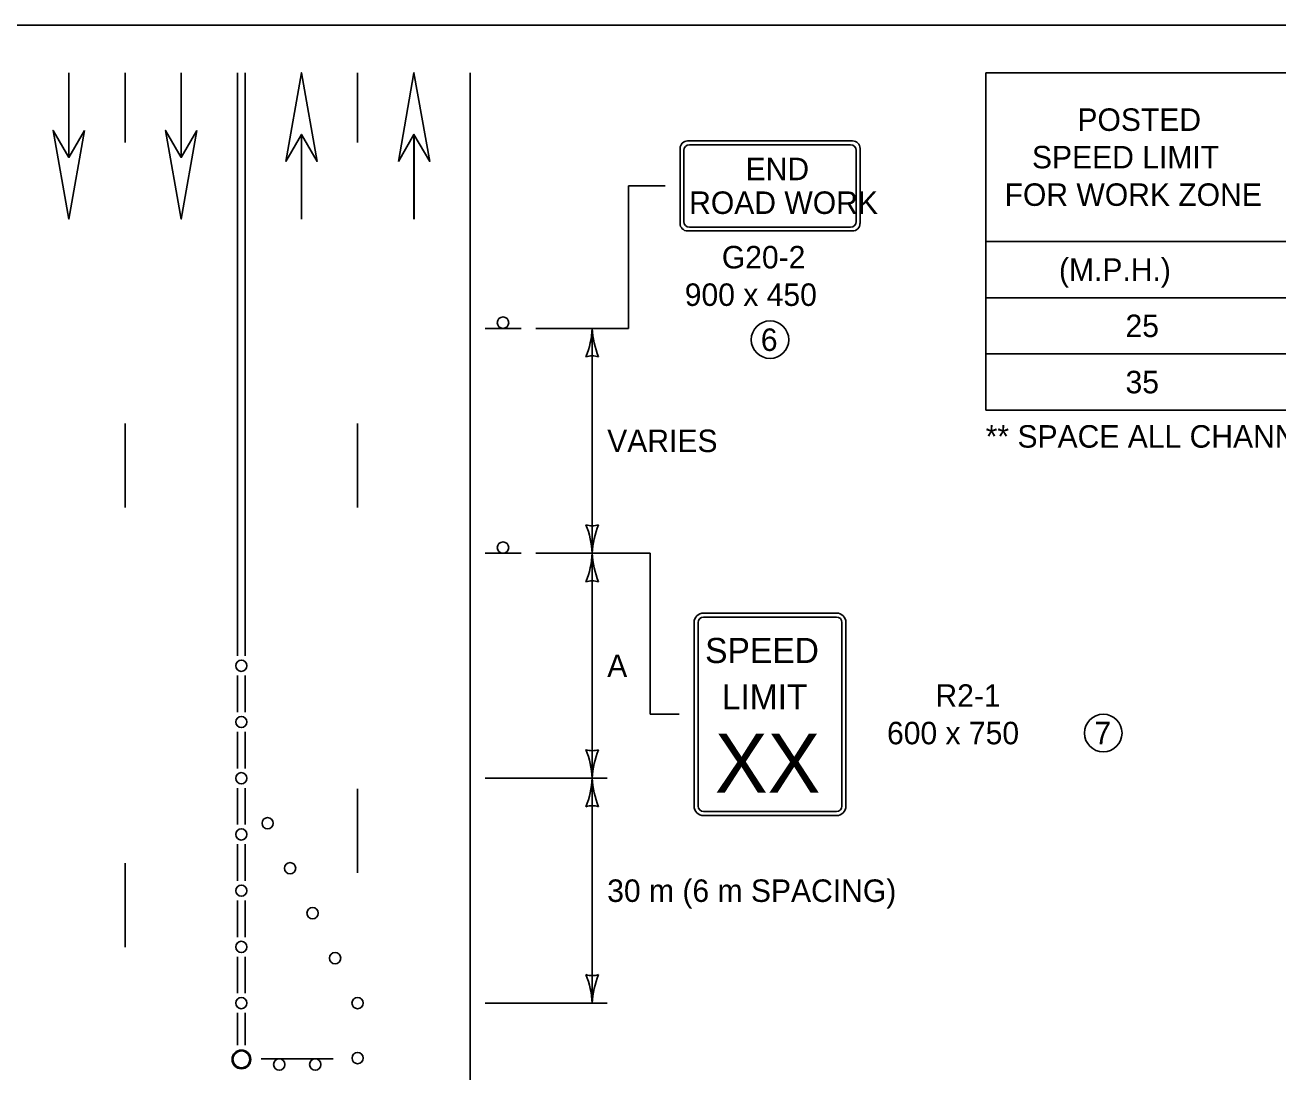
# Model space of a CAD drawing. Extents: x 49991.4 to 50021, y 49987.6 to 50011.4.
# Drawn here: x 50009.922 to 50013.265, y 49996.207 to 49998.999 of the extents above; entities that cross this region are included whole.
import ezdxf

# ---------------------------------------------------------------- set-up
doc = ezdxf.new("R2010")
doc.units = 0
for name, color, linetype in [('Level 1', 7, 'Continuous'), ('Level 2', 7, 'Continuous'), ('Level 3', 7, 'Continuous')]:
    doc.layers.add(name, color=color, linetype=linetype)

msp = doc.modelspace()

# ---------------------------------------------------------------- linework, layer by layer
at = {"layer": 'Level 1'}
for p, q in [((50010.0383, 49998.8719), (50010.0383, 49998.646)), ((50010.0387, 49998.8719), (50010.0387, 49998.646)), ((50010.1892, 49998.686), (50010.1892, 49998.8719)), ((50010.3383, 49998.8719), (50010.3383, 49998.646)), ((50010.3387, 49998.8719), (50010.3387, 49998.646)), ((50010.489, 49997.3163), (50010.489, 49998.8719)), ((50010.509, 49997.3163), (50010.509, 49998.8719)), ((50010.8092, 49998.686), (50010.8092, 49998.8719)), ((50011.109, 49995.0313), (50011.109, 49998.8719)), ((50010.6591, 49998.4818), (50010.6591, 49998.7077)), ((50010.6595, 49998.4818), (50010.6595, 49998.7077)), ((50010.9595, 49998.4818), (50010.9595, 49998.7077)), ((50010.9599, 49998.4818), (50010.9599, 49998.7077)), ((50011.6695, 49998.47), (50011.6695, 49998.67)), ((50011.6795, 49998.475), (50011.6795, 49998.665)), ((50012.1295, 49998.69), (50011.6895, 49998.69)), ((50012.1245, 49998.68), (50011.6945, 49998.68)), ((50012.1395, 49998.665), (50012.1395, 49998.475)), ((50012.1495, 49998.67), (50012.1495, 49998.47)), ((50012.1294, 49998.45), (50011.6894, 49998.45)), ((50012.1245, 49998.46), (50011.6945, 49998.46)), ((50011.245, 49998.1901), (50011.149, 49998.1901)), ((50010.1892, 49997.712), (50010.1892, 49997.936)), ((50010.8092, 49997.712), (50010.8092, 49997.936)), ((50011.245, 49997.5901), (50011.149, 49997.5901)), ((50011.7322, 49997.4307), (50012.0866, 49997.4307)), ((50011.9094, 49997.4307), (50011.9094, 49997.4307)), ((50011.7068, 49996.9158), (50011.7068, 49997.4053)), ((50011.7174, 49996.9158), (50011.7174, 49997.4053)), ((50011.7322, 49997.4201), (50012.0866, 49997.4201)), ((50012.1014, 49997.4053), (50012.1014, 49996.9158)), ((50012.1119, 49997.4053), (50012.1119, 49996.9158)), ((50010.4888, 49997.1663), (50010.4888, 49997.2639)), ((50010.5088, 49997.1663), (50010.5088, 49997.2639)), ((50010.4888, 49997.0163), (50010.4888, 49997.1139)), ((50010.5088, 49997.0163), (50010.5088, 49997.1139)), ((50010.4888, 49996.8663), (50010.4888, 49996.9639)), ((50010.5088, 49996.8663), (50010.5088, 49996.9639)), ((50010.8092, 49996.738), (50010.8092, 49996.962)), ((50012.0866, 49996.9011), (50011.7322, 49996.9011)), ((50012.0866, 49996.8905), (50011.7322, 49996.8905)), ((50010.4888, 49996.7163), (50010.4888, 49996.8139)), ((50010.5088, 49996.7163), (50010.5088, 49996.8139)), ((50010.1892, 49996.5391), (50010.1892, 49996.7631)), ((50010.4888, 49996.5663), (50010.4888, 49996.6639)), ((50010.5088, 49996.5663), (50010.5088, 49996.6639)), ((50010.4888, 49996.4163), (50010.4888, 49996.514)), ((50010.5088, 49996.4163), (50010.5088, 49996.514)), ((50010.4888, 49996.2781), (50010.4888, 49996.364)), ((50010.5088, 49996.2781), (50010.5088, 49996.364)), ((50010.6481, 49996.2415), (50010.5521, 49996.2415)), ((50010.7441, 49996.2415), (50010.6481, 49996.2415))]:
    msp.add_line(p, q, dxfattribs=at)
for points in [[(49999.3835, 49998.9992), (50016.7501, 49998.9992), (50016.7501, 49987.7988), (49999.3835, 49987.7988)], [(50010.6175, 49998.6354), (50010.6591, 49998.8719), (50010.7011, 49998.6354), (50010.6591, 49998.7076)], [(50010.9179, 49998.6354), (50010.9595, 49998.8719), (50011.0015, 49998.6354), (50010.9595, 49998.7076)], [(50010.0803, 49998.7183), (50010.0387, 49998.4818), (50009.9967, 49998.7183), (50010.0387, 49998.6461)], [(50010.3803, 49998.7183), (50010.3387, 49998.4818), (50010.2967, 49998.7183), (50010.3387, 49998.6461)]]:
    msp.add_lwpolyline(points, close=True, dxfattribs=at)
for centre, radius in [((50011.197, 49998.2053), 0.0152), ((50011.197, 49997.6053), 0.0152), ((50010.4988, 49997.2901), 0.015), ((50010.4988, 49997.1401), 0.015), ((50010.4988, 49996.9901), 0.015), ((50010.569, 49996.8701), 0.015), ((50010.4988, 49996.8401), 0.015), ((50010.629, 49996.7501), 0.015), ((50010.4988, 49996.6901), 0.015), ((50010.6889, 49996.6301), 0.015), ((50010.4988, 49996.5401), 0.015), ((50010.7489, 49996.5101), 0.015), ((50010.4988, 49996.3901), 0.015), ((50010.8089, 49996.3901), 0.015), ((50010.499, 49996.2401), 0.025), ((50010.499, 49996.2401), 0.0225), ((50010.499, 49996.2401), 0.0225), ((50010.8091, 49996.2435), 0.015), ((50010.6001, 49996.2263), 0.0152), ((50010.6961, 49996.2263), 0.0152)]:
    msp.add_circle(centre, radius, dxfattribs=at)
for centre, radius, start, end in [((50011.6895, 49998.67), 0.02, 90, 180), ((50011.6945, 49998.665), 0.015, 90, 180), ((50012.1245, 49998.665), 0.015, 360, 90), ((50012.1295, 49998.67), 0.02, 360, 90), ((50011.6894, 49998.47), 0.02, 180, 270), ((50011.6945, 49998.475), 0.015, 180, 270), ((50012.1245, 49998.475), 0.015, 270, 360), ((50012.1294, 49998.47), 0.02, 270, 360), ((50011.7322, 49997.4053), 0.0253, 90, 180), ((50012.0866, 49997.4053), 0.0253, 360, 90), ((50011.7322, 49997.4053), 0.0148, 90, 180), ((50012.0866, 49997.4053), 0.0148, 360, 90), ((50011.7322, 49996.9158), 0.0253, 180, 270), ((50011.7322, 49996.9158), 0.0148, 180, 270), ((50012.0866, 49996.9158), 0.0148, 270, 360), ((50012.0866, 49996.9158), 0.0253, 270, 360), ((50010.499, 49996.2401), 0.025, 0, 180), ((50010.499, 49996.2401), 0.0225, 356.6361, 176.6361), ((50010.499, 49996.2401), 0.025, 180, 0), ((50010.499, 49996.2401), 0.0225, 176.6361, 356.6361)]:
    msp.add_arc(centre, radius, start, end, dxfattribs=at)
at = {"layer": 'Level 2'}
for p, q in [((50012.4848, 49998.8719), (50016.4148, 49998.8719)), ((50012.4848, 49998.8719), (50012.4848, 49997.9719)), ((50012.4848, 49998.4219), (50016.4148, 49998.4219)), ((50012.4848, 49998.2719), (50016.4148, 49998.2719)), ((50012.4848, 49998.1219), (50016.4148, 49998.1219)), ((50012.4848, 49997.9719), (50016.4148, 49997.9719))]:
    msp.add_line(p, q, dxfattribs=at)
for centre in [(50011.9094, 49998.1599), (50012.7985, 49997.1106)]:
    msp.add_circle(centre, 0.0501, dxfattribs=at)
at = {"layer": 'Level 3'}
for p, q in [((50011.5315, 49998.1901), (50011.5315, 49998.57)), ((50011.5315, 49998.57), (50011.6295, 49998.57)), ((50011.285, 49998.1901), (50011.5315, 49998.1901)), ((50011.435, 49997.5901), (50011.435, 49998.1901)), ((50011.285, 49997.5901), (50011.5895, 49997.5901)), ((50011.435, 49996.9901), (50011.435, 49997.5901)), ((50011.6668, 49997.1606), (50011.5895, 49997.1606)), ((50011.149, 49996.9901), (50011.475, 49996.9901)), ((50011.435, 49996.3901), (50011.435, 49996.9901)), ((50011.149, 49996.3901), (50011.475, 49996.3901))]:
    msp.add_line(p, q, dxfattribs=at)
msp.add_lwpolyline([(50011.5895, 49997.5901), (50011.5895, 49997.1606)], dxfattribs=at)
for centre, radius, start, end in [((50011.2129, 49998.1993), 0.2223, 337.456, 357.6395), ((50011.6677, 49998.2016), 0.233, 182.8273, 202.0772), ((50011.435, 49998.0619), 0.0548, 72.1388, 107.8612), ((50011.435, 49997.7184), 0.0548, 252.1388, 287.8612), ((50011.2023, 49997.5787), 0.233, 2.8273, 22.0772), ((50011.6572, 49997.581), 0.2223, 157.456, 177.6395), ((50011.2129, 49997.5993), 0.2223, 337.456, 357.6395), ((50011.6677, 49997.6016), 0.233, 182.8273, 202.0772), ((50011.435, 49997.4619), 0.0548, 72.1388, 107.8612), ((50011.435, 49997.1184), 0.0548, 252.1388, 287.8612), ((50011.2023, 49996.9787), 0.233, 2.8273, 22.0772), ((50011.6572, 49996.981), 0.2223, 157.456, 177.6395), ((50011.2023, 49997.0016), 0.233, 337.9228, 357.1727), ((50011.6572, 49996.9993), 0.2223, 182.3605, 202.544), ((50011.435, 49996.8619), 0.0548, 72.1388, 107.8612), ((50011.2129, 49996.381), 0.2223, 2.3605, 22.544), ((50011.435, 49996.5184), 0.0548, 252.1388, 287.8612), ((50011.6677, 49996.3787), 0.233, 157.9228, 177.1727)]:
    msp.add_arc(centre, radius, start, end, dxfattribs=at)

# ---------------------------------------------------------------- texts
at = {"layer": 'Level 1'}
for s, height, p in [('END', 0.06, (50011.8443, 49998.5854)), ('ROAD WORK', 0.06, (50011.6936, 49998.4954)), ('SPEED', 0.06695, (50011.7363, 49997.2974)), ('LIMIT', 0.06695, (50011.7806, 49997.1736)), ('XX', 0.15773, (50011.7623, 49996.9516))]:
    msp.add_text(s, height=height, rotation=360, dxfattribs=at).set_placement(p)
at = {"layer": 'Level 2'}
for s, p in [('POSTED', (50012.7295, 49998.7169)), ('SPEED LIMIT', (50012.6082, 49998.6169)), ('FOR WORK ZONE', (50012.5352, 49998.5169)), ('(M.P.H.)', (50012.6803, 49998.3169)), ('25', (50012.8578, 49998.1669)), ('35', (50012.8579, 49998.0169)), ('** SPACE ALL CHANNELIZING DEVICES AT "G" UNLESS OTHERWISE NOTED.', (50012.4848, 49997.8719)), ('VARIES', (50011.475, 49997.8601)), ('A', (50011.475, 49997.2601)), ('R2-1', (50012.3507, 49997.1806)), ('600 x 750', (50012.2215, 49997.0806))]:
    msp.add_text(s, height=0.06, dxfattribs=at).set_placement(p)
for s, p in [('G20-2', (50011.7808, 49998.35)), ('900 x 450', (50011.6819, 49998.25)), ('6', (50011.8849, 49998.1299)), ('7', (50012.7747, 49997.0806)), ('30 m (6 m SPACING)', (50011.475, 49996.6601))]:
    msp.add_text(s, height=0.06, rotation=360, dxfattribs=at).set_placement(p)

doc.saveas('drawing.dxf')
